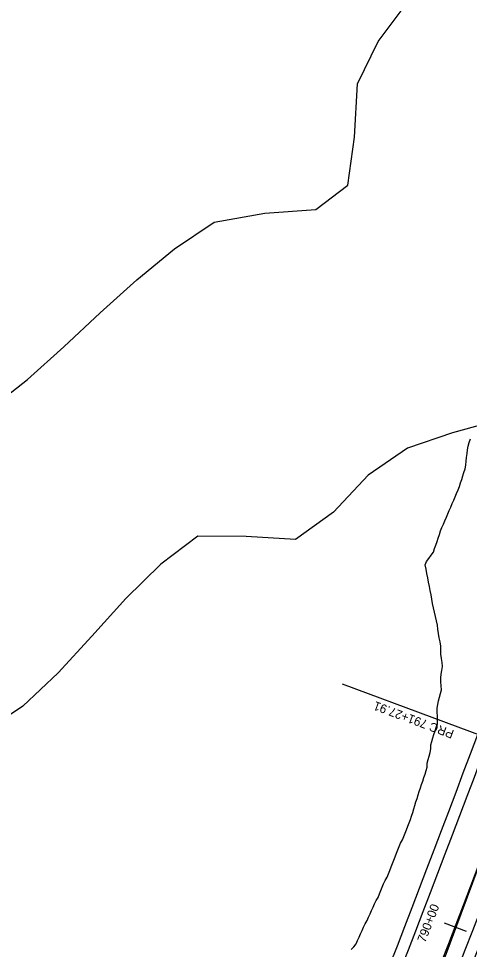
# Model space of a CAD drawing. Extents: x 1237212 to 1293764, y 379349 to 410301.
# Drawn here: x 1282851 to 1283157, y 403256 to 403888 of the extents above; entities that cross this region are included whole.
import ezdxf

# ---------------------------------------------------------------- set-up
doc = ezdxf.new("R2010")
doc.units = 0
for name, color, linetype in [('B-Tbl-Title Block', 7, 'Continuous'), ('B-Title Block (No Plot)', 7, 'Continuous'), ('R_Axis_Annotation', 7, 'Continuous'), ('R_Exist Surface', 7, 'Continuous'), ('R_Grid', 7, 'Continuous'), ('R_Grid Annot', 7, 'Continuous'), ('R_Shld', 7, 'Continuous')]:
    doc.layers.add(name, color=color, linetype=linetype)

msp = doc.modelspace()

# ---------------------------------------------------------------- linework, layer by layer
at = {"layer": 'B-Tbl-Title Block'}
for radius in [11435.16, 11471.16]:
    msp.add_arc((1272453.81, 407390.3), radius, 337.333333, 339.572534, dxfattribs=at)
at = {"layer": 'B-Title Block (No Plot)'}
msp.add_arc((1272453.81, 407390.3), 11459.16, 337.333333, 339.572534, dxfattribs=at)
msp.add_arc((1272453.81, 407390.3), 11459.16, 337.333333, 339.572534, dxfattribs=at)
at = {"layer": 'R_Axis_Annotation'}
for points in [[(1282830.94, 403622.96), (1282856.68, 403643.14), (1282881.42, 403665.2), (1282906.01, 403688.24), (1282930.95, 403710.79), (1282956.59, 403731.88), (1282983.52, 403749.85), (1283017.78, 403755.98), (1283052.48, 403758.51), (1283074.12, 403775.08), (1283078.65, 403807.66), (1283080.73, 403843.84), (1283094.89, 403872.57), (1283114.44, 403898.78)], [(1283176.57, 403615.54), (1283145.16, 403606.85), (1283114.59, 403596.32), (1283087.91, 403577.98), (1283064.51, 403552.87), (1283038.58, 403534.34), (1283005.07, 403536.51), (1282972.47, 403536.61), (1282947.13, 403517.72), (1282923.44, 403494.25), (1282900.45, 403468.77), (1282877.65, 403443.71), (1282853.66, 403421.16), (1282827.73, 403404.04)]]:
    msp.add_lwpolyline(points, dxfattribs=at)
at = {"layer": 'R_Exist Surface'}
msp.add_lwpolyline([(1283076.35, 403255.79), (1283078.24, 403257.72), (1283079.82, 403259.77), (1283080.83, 403262.05), (1283081.84, 403264.33), (1283082.85, 403266.6), (1283083.86, 403268.88), (1283084.87, 403271.15), (1283085.95, 403273.4), (1283087.28, 403275.55), (1283088.3, 403277.83), (1283089.32, 403280.1), (1283090.34, 403282.37), (1283091.37, 403284.64), (1283092.39, 403286.91), (1283093.49, 403289.15), (1283094.81, 403291.32), (1283095.72, 403293.63), (1283096.63, 403295.94), (1283097.54, 403298.26), (1283098.46, 403300.57), (1283099.5, 403302.84), (1283100.8, 403305), (1283101.71, 403307.32), (1283102.62, 403309.63), (1283103.53, 403311.95), (1283104.44, 403314.27), (1283105.35, 403316.58), (1283106.26, 403318.9), (1283107.17, 403321.21), (1283108.07, 403323.53), (1283108.98, 403325.85), (1283110.01, 403328.12), (1283111.32, 403330.28), (1283112.23, 403332.6), (1283113.14, 403334.91), (1283114.04, 403337.23), (1283114.95, 403339.55), (1283115.85, 403341.87), (1283116.7, 403344.21), (1283117.53, 403346.55), (1283118.26, 403348.94), (1283119, 403351.32), (1283119.73, 403353.7), (1283120.47, 403356.08), (1283121.2, 403358.47), (1283121.93, 403360.85), (1283122.67, 403363.23), (1283123.42, 403365.6), (1283124.28, 403367.94), (1283125.13, 403370.28), (1283125.86, 403372.66), (1283126.59, 403375.04), (1283127.33, 403377.43), (1283128, 403379.83), (1283128.13, 403382.44), (1283128.63, 403384.91), (1283129.35, 403387.3), (1283130.06, 403389.68), (1283130.45, 403392.2), (1283130.52, 403394.82), (1283131.11, 403397.26), (1283131.9, 403399.62), (1283132.69, 403401.98), (1283133.48, 403404.34), (1283134.26, 403406.7), (1283135.04, 403409.06), (1283135.1, 403411.7), (1283135.01, 403414.41), (1283134.92, 403417.12), (1283134.83, 403419.84), (1283135.22, 403422.38), (1283135.84, 403424.83), (1283136.46, 403427.28), (1283137.07, 403429.74), (1283137.69, 403432.19), (1283137.6, 403434.91), (1283137.33, 403437.7), (1283137.23, 403440.42), (1283137.63, 403442.96), (1283138.04, 403445.49), (1283138.44, 403448.03), (1283138.28, 403450.77), (1283137.83, 403453.63), (1283137.38, 403456.49), (1283137.29, 403459.21), (1283137.28, 403461.9), (1283136.79, 403464.78), (1283136.24, 403467.68), (1283135.68, 403470.58), (1283135.28, 403473.42), (1283135.13, 403476.17), (1283134.45, 403479.12), (1283133.76, 403482.08), (1283133.07, 403485.03), (1283132.38, 403487.99), (1283131.78, 403490.91), (1283131.23, 403493.82), (1283130.67, 403496.73), (1283130.12, 403499.63), (1283129.56, 403502.54), (1283129, 403505.45), (1283128.44, 403508.37), (1283127.88, 403511.28), (1283127.31, 403514.2), (1283126.74, 403517.12), (1283127.7, 403519.45), (1283129.23, 403521.57), (1283130.75, 403523.69), (1283132.27, 403525.8), (1283133.13, 403528.18), (1283133.93, 403530.57), (1283134.73, 403532.97), (1283135.52, 403535.36), (1283136.32, 403537.76), (1283137.12, 403540.16), (1283138.12, 403542.48), (1283139.12, 403544.79), (1283140.11, 403547.11), (1283141.11, 403549.43), (1283142.1, 403551.75), (1283143.1, 403554.07), (1283144.09, 403556.4), (1283145.08, 403558.72), (1283146.06, 403561.04), (1283147.05, 403563.37), (1283148.03, 403565.69), (1283149.01, 403568.01), (1283149.9, 403570.37), (1283150.69, 403572.78), (1283151.48, 403575.18), (1283152.26, 403577.58), (1283153.04, 403579.98), (1283153.83, 403582.38), (1283154.2, 403584.94), (1283154.52, 403587.53), (1283154.83, 403590.11), (1283155.14, 403592.7), (1283155.45, 403595.29), (1283155.91, 403597.82), (1283156.65, 403600.24), (1283157.38, 403602.66)], dxfattribs=at)
at = {"layer": 'R_Grid'}
for points in [[(1283192.36, 403390.81), (1283070.53, 403436.18)], [(1283192.36, 403390.81), (1283070.53, 403436.18)], [(1283027.89, 402974.29), (1283114.2, 403180.94), (1283192.36, 403390.81)]]:
    msp.add_lwpolyline(points, dxfattribs=at)
at = {"layer": 'R_Grid Annot'}
msp.add_lwpolyline([(1283139.58, 403274.07), (1283154.51, 403268.32)], dxfattribs=at)
msp.add_lwpolyline([(1283139.58, 403274.07), (1283154.51, 403268.32)], dxfattribs=at)
at = {"layer": 'R_Shld'}
for radius in [11427.16, 11479.16]:
    msp.add_arc((1272453.81, 407390.3), radius, 337.333333, 339.572534, dxfattribs=at)

# ---------------------------------------------------------------- texts
at = {"layer": 'R_Grid'}
msp.add_text('PRC 791+27.91', height=6, rotation=159.57253, dxfattribs=at).set_placement((1283146.79, 403404.57))
msp.add_text('PRC 791+27.91', height=6, rotation=159.57253, dxfattribs=at).set_placement((1283146.79, 403404.57))
at = {"layer": 'R_Grid Annot'}
msp.add_text('790+00', height=6, rotation=68.93299, dxfattribs=at).set_placement((1283126.71, 403260.12))

doc.saveas('drawing.dxf')
